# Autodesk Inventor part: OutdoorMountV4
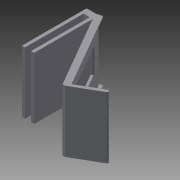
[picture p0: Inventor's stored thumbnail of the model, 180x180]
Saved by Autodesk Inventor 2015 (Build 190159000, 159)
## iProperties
Created: 2017-04
Part Number: OutdoorMountV4
Material: Generisch
Document SubType Name: Modeling
Designer: Andreas
Density: 1 g/cm^3
Appearance: Vorgabe
Author: Andreas
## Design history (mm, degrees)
sketch "Skizze1"
  geometry: L1 (0, 0)-(0, 105); L2 (0, 105)-(20, 105); L3 (0, 0)-(5, 0); L4 (5, 0)-(5, 95); L5 (5, 95)-(15, 95); L6 (15, 95)-(15, 0); L7 (15, 0)-(20, 0); L8 (20, 0)-(20, 95); L9 (25, 105)-(143.136, 105); L10 (20, 95)-(73.912, 1.622); L11 (20, 95)-(127.824, 95); L12 (20, 105)-(141.313, 105); L13 (20, 105)-(90, -16.244); L14 (20, 105)-(160, 105); L15 (90, -16.244)-(133.301, 8.756); L16 (133.301, 8.756)-(135.801, 4.426); L17 (135.801, 4.426)-(91.34, -21.244); L18 (91.34, -21.244)-(87.113, -21.244); L19 (87.113, -21.244)-(73.912, 1.622)
  constraints: 38 end point, 8 horizontal, 6 perpendicular, 2 equal length, 2 vertical, 1 parallel, 1 point on line
  dimensions: "d0" = 105 distance of L1.start L1.end; "d2" = 5 distance of L1.start L3.end; "d3" = 95 distance of L3.end L4.end; "d4" = 10 distance of L4.end L5.end; "d5" = 5 distance of L6.end L7.end; "d6" = 95 distance of L7.end L8.end; "d27" = 60 deg angle of L10 L11; "d35" = 20 distance of L1.end L2.end; "d69" = 140 distance of L2.end L13.end; "d70" = 60 deg angle of L13 L14; "d71" = 50 distance of L13.end L15.end; "d72" = 90 deg angle of L15 L13 (derived); "d75" = 5 distance of L15.end L16.end; "d90" = 5 distance from line of L18 L13.end
extrude "Extrusion1" new body sketch "Skizze1" distance "d39" = 100; taper "d40" = 0 deg
sketch "Skizze4"
  geometry: L1 (-20, 105)-(-90, -16.244) reference; L2 (-24.33, 107.5)-(-15, 105); L3 (-15, 105)-(-20, 105); L4 (0, 105)-(-20, 105) reference; L5 (-24.33, 107.5)-(-94.33, -13.744); L6 (-94.33, -13.744)-(-90, -16.244); L7 (-90, -16.244)-(-133.301, 8.756) reference; 1 further point
  constraints: 8 end point, 2 collinear
  dimensions: "d87" = 140 distance of L2.start L5.end
fillet "Rundung3" dims "d57" = 2
sketch "Skizze5"
  geometry: L1 (27.5, 94.399)-(67.5, 94.399); L2 (67.5, 94.399)-(67.5, -5.601); L3 (67.5, -5.601)-(27.5, -5.601); L4 (27.5, -5.601)-(27.5, 94.399); 3 further points
  constraints: 8 end point, 2 parallel, 1 horizontal, 1 perpendicular
  dimensions: "d79" = 40 distance of L2.end L3.end; "d80" = 100 distance of L1.end L2.end
extrude "Extrusion5" cut sketch "Skizze5" distance "d81" = 5; taper "d82" = 0 deg
extrude "Extrusion6" join sketch "Skizze4" distance "d83" = 2.5; taper "d84" = 0 deg
fillet "Rundung10" dims "d85" = 2
fillet "Rundung11" dims "d86" = 2
sketch "Skizze6"
  geometry: L1 (22.848, 107.103)-(15, 105) reference; L2 (18.845, 105)-(15, 105) reference; L3 (90, -16.244)-(20.577, 104) reference; L4 (94.33, -13.744)-(90, -16.244) reference; L5 (94.33, -13.744)-(25.097, 106.171) reference; A1 r 2 centre (23.365, 105.171) between (25.097, 106.171) and (22.848, 107.103) reference; A2 r 2 centre (18.845, 103) between (20.577, 104) and (18.845, 105) reference; 1 further point
extrude "Extrusion7" join sketch "Skizze6" distance "d88" = 2.5; taper "d89" = 0 deg
node "Volumenkörper1"
node "Projizierte Kontur1"
